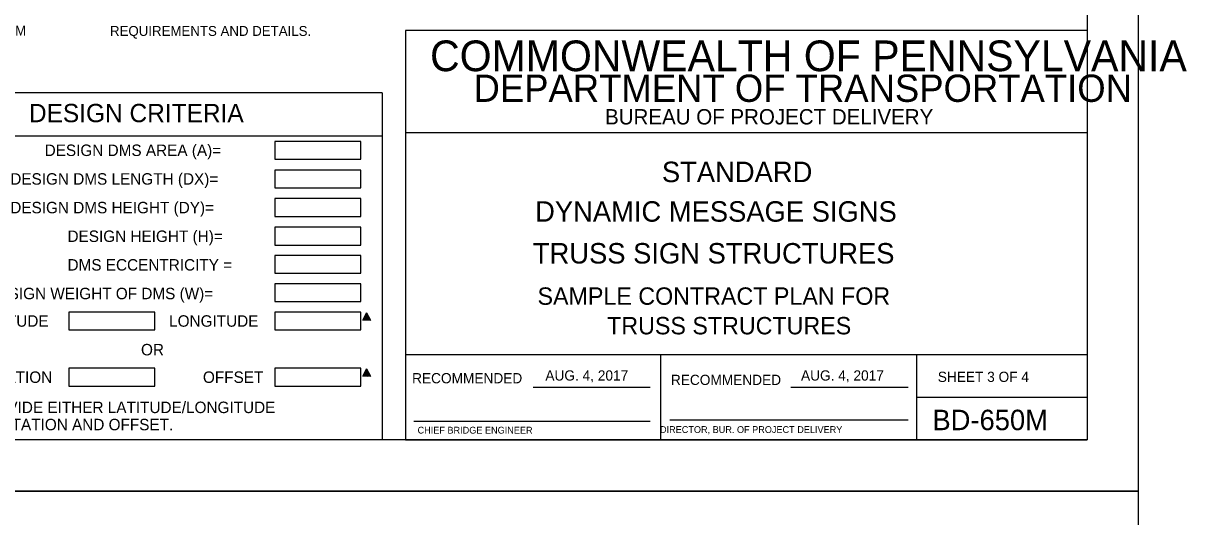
# Model space of a CAD drawing. Extents: x 3831399 to 3833095, y 499014 to 500202.
# Drawn here: x 3832754.1 to 3833095.4, y 499600.5 to 499745.2 of the extents above; entities that cross this region are included whole.
import ezdxf

# ---------------------------------------------------------------- set-up
doc = ezdxf.new("R2010")
doc.units = 0
for name, color, linetype in [('10', 7, 'Continuous'), ('2', 7, 'Continuous'), ('DIM TXT', 7, 'Continuous'), ('PLT-BNDY', 7, 'Continuous')]:
    doc.layers.add(name, color=color, linetype=linetype)

msp = doc.modelspace()

# ---------------------------------------------------------------- linework, layer by layer
at = {"layer": '2'}
for p, q in [((3833066.16, 500187.03), (3833066.16, 499623.03)), ((3833066.16, 499743.03), (3832866.16, 499743.03)), ((3832866.16, 499743.03), (3832866.16, 499623.03)), ((3833066.16, 499713.03), (3832866.16, 499713.03)), ((3833066.16, 499648.03), (3832866.16, 499648.03)), ((3832941.16, 499623.03), (3832941.16, 499648.03)), ((3833016.16, 499648.03), (3833016.16, 499623.03)), ((3832903.62, 499638.53), (3832938.03, 499638.53)), ((3832979.24, 499638.53), (3833013.65, 499638.53)), ((3833016.16, 499635.53), (3833066.16, 499635.53)), ((3832868.66, 499628.53), (3832938.03, 499628.53)), ((3832943.79, 499628.9), (3833013.65, 499628.9)), ((3833066.16, 499623.03), (3832280.16, 499623.03)), ((3832866.16, 499623.03), (3833066.16, 499623.03))]:
    msp.add_line(p, q, dxfattribs=at)
at = {"layer": 'DIM TXT'}
for p, q in [((3832859.35, 499724.78), (3832733.69, 499724.78)), ((3832859.35, 499724.78), (3832859.35, 499623.03)), ((3832733.69, 499712.15), (3832859.35, 499712.15)), ((3832853.96, 499658.65), (3832855.1, 499659.78)), ((3832854.23, 499659.18), (3832855.01, 499659.96)), ((3832854.49, 499659.71), (3832854.92, 499660.13)), ((3832854.76, 499660.24), (3832854.83, 499660.31)), ((3832853.76, 499658.18), (3832855.18, 499659.6)), ((3832854.02, 499658.18), (3832855.27, 499659.43)), ((3832854.29, 499658.18), (3832855.36, 499659.25)), ((3832854.55, 499658.18), (3832855.45, 499659.07)), ((3832854.82, 499658.18), (3832855.54, 499658.9)), ((3832855.08, 499658.18), (3832855.63, 499658.72)), ((3832855.35, 499658.18), (3832855.71, 499658.54)), ((3832855.61, 499658.18), (3832855.8, 499658.37)), ((3832855.88, 499658.18), (3832855.89, 499658.19)), ((3832853.76, 499641.71), (3832855.18, 499643.14)), ((3832853.96, 499642.19), (3832855.1, 499643.32)), ((3832854.02, 499641.71), (3832855.27, 499642.97)), ((3832854.23, 499642.72), (3832855.01, 499643.5)), ((3832854.29, 499641.71), (3832855.36, 499642.79)), ((3832854.49, 499643.25), (3832854.92, 499643.67)), ((3832854.76, 499643.78), (3832854.83, 499643.85)), ((3832854.55, 499641.71), (3832855.45, 499642.61)), ((3832854.82, 499641.71), (3832855.54, 499642.43)), ((3832855.08, 499641.71), (3832855.63, 499642.26)), ((3832855.35, 499641.71), (3832855.71, 499642.08)), ((3832855.61, 499641.71), (3832855.8, 499641.9)), ((3832855.88, 499641.71), (3832855.89, 499641.73)), ((3832859.35, 499623.03), (3832733.69, 499623.03))]:
    msp.add_line(p, q, dxfattribs=at)
for points in [[(3832827.9, 499705.32), (3832853.09, 499705.32), (3832853.09, 499710.57), (3832827.9, 499710.57)], [(3832827.9, 499696.93), (3832853.09, 499696.93), (3832853.09, 499702.17), (3832827.9, 499702.17)], [(3832827.9, 499688.53), (3832853.09, 499688.53), (3832853.09, 499693.78), (3832827.9, 499693.78)], [(3832827.9, 499680.13), (3832853.09, 499680.13), (3832853.09, 499685.38), (3832827.9, 499685.38)], [(3832827.9, 499671.91), (3832853.09, 499671.91), (3832853.09, 499677.16), (3832827.9, 499677.16)], [(3832827.9, 499663.59), (3832853.09, 499663.59), (3832853.09, 499668.84), (3832827.9, 499668.84)], [(3832767.45, 499655.27), (3832792.64, 499655.27), (3832792.64, 499660.52), (3832767.45, 499660.52)], [(3832827.9, 499655.27), (3832853.09, 499655.27), (3832853.09, 499660.52), (3832827.9, 499660.52)], [(3832853.73, 499658.18), (3832854.81, 499660.35), (3832855.9, 499658.18)], [(3832767.45, 499638.81), (3832792.64, 499638.81), (3832792.64, 499644.06), (3832767.45, 499644.06)], [(3832827.9, 499638.81), (3832853.09, 499638.81), (3832853.09, 499644.06), (3832827.9, 499644.06)], [(3832853.73, 499641.71), (3832854.81, 499643.88), (3832855.9, 499641.71)]]:
    msp.add_lwpolyline(points, close=True, dxfattribs=at)
at = {"layer": 'PLT-BNDY'}
for points in [[(3832240.16, 500202.03), (3833081.16, 500202.03), (3833081.16, 499608.03), (3832240.16, 499608.03)], [(3832240.16, 499608.03), (3833081.16, 499608.03), (3833081.16, 499014.03), (3832240.16, 499014.03)]]:
    msp.add_lwpolyline(points, close=True, dxfattribs=at)

# ---------------------------------------------------------------- texts
at = {"layer": '10'}
for s, height, p in [('STANDARD ', 6, (3832941.43, 499698.62)), ('DYNAMIC MESSAGE SIGNS', 6, (3832904.23, 499687.02)), ('TRUSS SIGN STRUCTURES', 6, (3832903.56, 499674.76)), ('SAMPLE CONTRACT PLAN FOR', 5.1, (3832904.94, 499662.66)), ('TRUSS STRUCTURES', 5.1, (3832925.36, 499653.99))]:
    msp.add_text(s, height=height, dxfattribs=at).set_placement(p)
at = {"layer": '2'}
for s, height, p in [('COMMONWEALTH OF PENNSYLVANIA', 9, (3832873.41, 499731.15)), ('DEPARTMENT OF TRANSPORTATION', 8.0002, (3832886.16, 499722.15)), ('BUREAU OF PROJECT DELIVERY', 4.5, (3832924.75, 499715.53)), ('AUG. 4, 2017', 3, (3832907.24, 499640.44)), ('AUG. 4, 2017', 3, (3832982.24, 499640.44)), ('SHEET 3 OF 4', 3, (3833022.36, 499640.04)), ('BD-650M', 6, (3833020.79, 499625.9)), ('CHIEF BRIDGE ENGINEER', 2.0002, (3832869.75, 499624.9)), ('   DIRECTOR, BUR. OF PROJECT DELIVERY', 2.0002, (3832938.63, 499625.08))]:
    msp.add_text(s, height=height, dxfattribs=at).set_placement(p)
for p in [(3832868.14, 499639.64), (3832944.07, 499639.15)]:
    msp.add_text('RECOMMENDED', height=3, rotation=360, dxfattribs=at).set_placement(p)
at = {"layer": 'DIM TXT'}
for s, height, p in [('SEE BC-745M', 2.9099, (3832729.61, 499741.61)), ('REQUIREMENTS AND DETAILS.', 2.9099, (3832779.51, 499741.49)), ('DESIGN CRITERIA', 5.3677, (3832755.72, 499716.19)), ('DESIGN DMS AREA (A)=', 3.3588, (3832760.34, 499706.28)), ('DESIGN DMS LENGTH (DX)=', 3.3588, (3832750.26, 499697.88)), ('DESIGN DMS HEIGHT (DY)=', 3.3588, (3832750.26, 499689.48)), ('DESIGN HEIGHT (H)=', 3.3588, (3832767.05, 499681.08)), ('DMS ECCENTRICITY =', 3.3588, (3832767.05, 499672.69)), ('DESIGN WEIGHT OF DMS (W)=', 3.3588, (3832743.54, 499664.29)), ('LATITUDE', 3.359, (3832739.78, 499656.23)), ('LONGITUDE', 3.359, (3832796.86, 499656.23)), ('OR', 3.359, (3832788.61, 499647.83)), ('STATION', 3.359, (3832743.11, 499639.76)), ('OFFSET', 3.359, (3832806.78, 499639.76)), ('PROVIDE EITHER LATITUDE/LONGITUDE', 3.3588, (3832739.68, 499630.91)), ('OR STATION AND OFFSET.', 3.3588, (3832739.68, 499625.87))]:
    msp.add_text(s, height=height, dxfattribs=at).set_placement(p)

doc.saveas('drawing.dxf')
